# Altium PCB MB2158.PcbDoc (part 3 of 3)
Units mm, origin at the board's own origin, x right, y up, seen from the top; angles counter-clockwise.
Board outline 43 x 60 mm, 4 copper layers (Top Layer, Signal Layer 1, Signal Layer 2, Bottom Layer), stack 1.539 mm thick; 117 components, 89 nets, 427 pads, 621 vias.
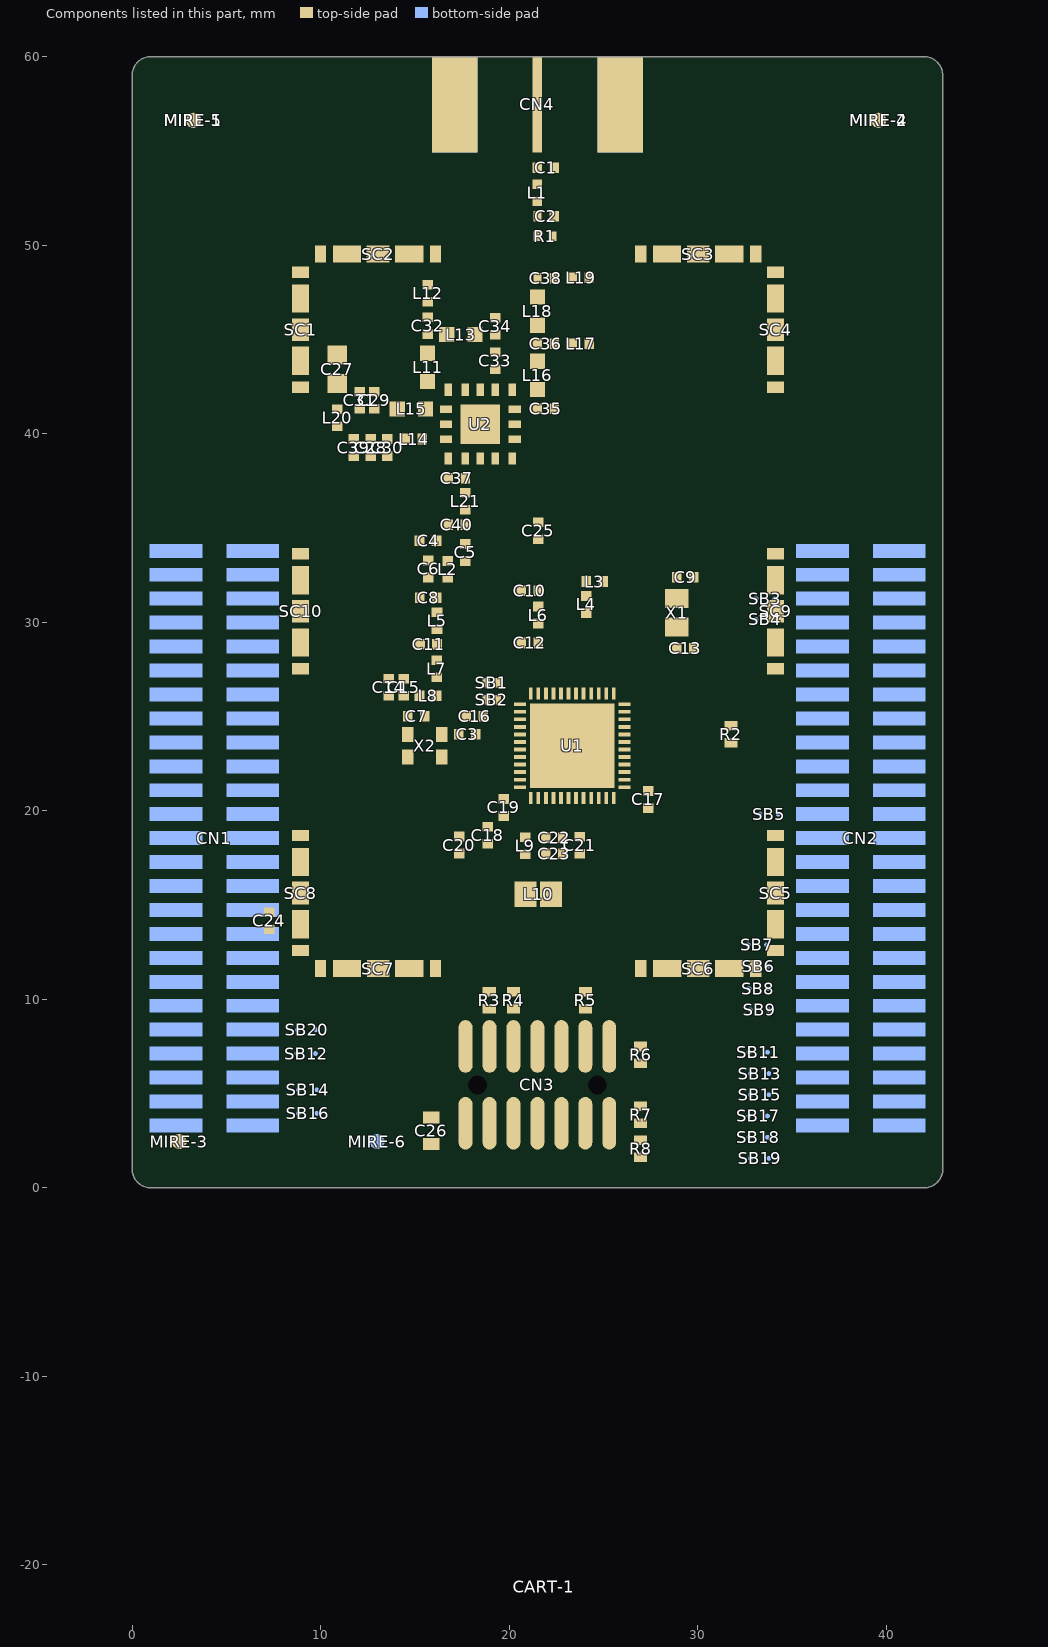
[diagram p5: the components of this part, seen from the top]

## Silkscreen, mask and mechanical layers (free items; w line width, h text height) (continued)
Drill Drawing:
  drawing of 189 lines, arcs and shapes, not listed
  text "Layer" at 107.14,109.1 h1.8
  text "Name" at 114.67,109.1 h1.8
  text "Material" at 129.227,109.1 h1.8
  text "Thickness" at 142.311,109.1 h1.8
  text "Constant" at 153.057,109.1 h1.8
  text "PCB SPECIFICATIONS :" at -42.216,108.312 h3
  text "Top Overlay" at 114.67,105.5 h1.8
  text "A.   MATERIAL :" at -42.216,104.312 h3
  text "FR-4" at -3.716,104.312 h3
  text "TG-170" at 12.784,104.312 h3
  text "X  TG-150" at 31.034,104.312 h3
  text "TG-140" at 47.034,104.312 h3
  text "Top Solder" at 114.67,101.9 h1.8
  text "Solder Resist" at 129.227,101.9 h1.8
  text "0.010mm" at 142.311,101.9 h1.8
  text "3.5" at 153.057,101.9 h1.8
  text "B.   MATERIAL FAMILY :" at -42.216,101.312 h3
  text "Ventec VT/47" at -3.716,101.312 h3
  text "C.   SOLDERMASK COLOR :" at -42.216,98.312 h3
  text "GREEN" at -3.716,98.312 h3
  text "X  BLUE" at 12.784,98.312 h3
  text "RED" at 31.034,98.312 h3
  text "BLACK" at 47.034,98.312 h3
  text "1" at 107.14,98.3 h1.8
  text "Top Layer" at 114.67,98.3 h1.8
  text "Copper" at 129.227,98.3 h1.8
  text "0.041mm" at 142.311,98.3 h1.8
  text "D.   SILKSCREEN COLOR :" at -42.216,95.312 h3
  text "X  WHITE" at -3.716,95.312 h3
  text "YELLOW" at 12.784,95.312 h3
  text "BLACK" at 31.034,95.312 h3
  text "Dielectric 1" at 114.67,94.7 h1.8
  text "FR4 VT-47" at 129.227,94.7 h1.8
  text "0.254mm" at 142.311,94.7 h1.8
  text "4" at 153.057,94.7 h1.8
  text "E.   SURFACE FINISH :" at -42.216,92.312 h3
  text "X  ENIG" at -3.716,92.312 h3
  text "IMMERSION SILVER" at 12.784,92.312 h3
  text "IMMERSION TIN" at 47.034,92.312 h3
  text "2" at 107.138,91.1 h1.8
  text "Signal Layer 1" at 114.67,91.1 h1.8
  text "Copper" at 129.227,91.1 h1.8
  text "0.018mm" at 142.311,91.1 h1.8
  text "HASL" at -3.716,89.312 h3
  text "HASL (PB-FREE)" at 12.784,89.312 h3
  text "GOLDEN FINGER" at 47.034,89.312 h3
  text "Dielectric 2" at 114.67,87.5 h1.8
  text "FR4 VT-47" at 129.227,87.5 h1.8
  text "0.914mm" at 142.311,87.5 h1.8
  text "4.3" at 153.057,87.5 h1.8
  text "F.   IMPEDANCE CONTROL :" at -42.216,86.312 h3
  text "NO" at -3.716,86.312 h3
  text "X  YES" at 12.784,86.312 h3
  text "3" at 107.14,83.9 h1.8
  text "Signal Layer 2" at 114.67,83.9 h1.8
  text "Copper" at 129.227,83.9 h1.8
  text "0.018mm" at 142.311,83.9 h1.8
  text "G.   THROUGH VIA :" at -42.216,83.312 h3
  text "PLUG THE VIAS WHICH ARE COVERED WITH SOLDERMASK ONE OR TWO SIDE." at -3.716,83.312 h3
  text "PLUG MATERIAL :" at -3.716,80.312 h3
  text "X  SOLDERMASK" at 21.784,80.312 h3
  text "NON-CONDUCTIVE EPOXY." at 47.034,80.312 h3
  text "Dielectric 3" at 114.67,80.3 h1.8
  text "FR4 VT-47" at 129.227,80.3 h1.8
  text "0.254mm" at 142.311,80.3 h1.8
  text "4" at 153.057,80.3 h1.8
  text "H.   STACK-UP :" at -42.216,77.312 h3
  text "SEE LAYER STACK-UP SEQUENCE FOR OVERALL THICKNESS." at -3.716,77.312 h3
  text "4" at 107.14,76.7 h1.8
  text "Bottom Layer" at 114.67,76.7 h1.8
  text "Copper" at 129.227,76.7 h1.8
  text "0.041mm" at 142.311,76.7 h1.8
  text "Bottom Solder" at 114.67,73.1 h1.8
  text "Solder Resist" at 129.227,73.1 h1.8
  text "0.010mm" at 142.311,73.1 h1.8
  text "3.5" at 153.057,73.1 h1.8
  text "Bottom Overlay" at 114.67,69.5 h1.8
  text "PCB : TYPE 3" at 125.413,56.046 h3
  text "ASPECT-RATIO, AXE Z :" at 125.413,50.546 h3
  text "6 :1 à 8 :1 / LEVEL \"B\"" at 125.432,43.799 h3
  text "MINIMUN PARAMETERS" at 125.425,38.075 h3
  text "DEFAULT" at 125.475,32.095 h3
  text "TRACKS : 0.150mm           / GAPS : 0.150mm" at 125.475,26.345 h3
  text "Symbol" at 64.337,15.508 h2.16
  text "Count" at 72.791,15.508 h2.16
  text "Hole Size" at 81.566,15.508 h2.16
  text "Plated" at 97.094,15.508 h2.16
  text "Hole Type" at 104.52,15.508 h2.16
  text "Drill Layer Pair" at 115.325,15.508 h2.16
  text "Via/Pad" at 135.794,15.508 h2.16
  text "Hole Length" at 144.651,15.508 h2.16
  text "593" at 72.791,11.781 h1.8
  text "0.20mm (7.87mil)" at 81.566,11.781 h1.8
  text "PTH" at 97.094,11.781 h1.8
  text "Round" at 104.52,11.781 h1.8
  text "Top Layer - Bottom Layer" at 115.325,11.781 h1.8
  text "Via" at 135.794,11.781 h1.8
  text "-" at 144.651,11.781 h1.8
  text "28" at 72.791,8.053 h1.8
  text "0.30mm (11.81mil)" at 81.566,8.053 h1.8
  text "PTH" at 97.094,8.053 h1.8
  text "Round" at 104.52,8.053 h1.8
  text "Top Layer - Bottom Layer" at 115.325,8.053 h1.8
  text "Via" at 135.794,8.053 h1.8
  text "-" at 144.651,8.053 h1.8
  text "2" at 72.791,4.325 h1.8
  text "1.00mm (39.37mil)" at 81.566,4.325 h1.8
  text "NPTH" at 97.094,4.325 h1.8
  text "Round" at 104.52,4.325 h1.8
  text "Top Layer - Bottom Layer" at 115.325,4.325 h1.8
  text "Pad" at 135.794,4.325 h1.8
  text "-" at 144.651,4.325 h1.8
  text "623 Total" at 72.791,0.597 h1.8

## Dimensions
1,0 to 1,60 on M2-Board Dimensions
0,59 to 43,59 on M2-Board Dimensions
